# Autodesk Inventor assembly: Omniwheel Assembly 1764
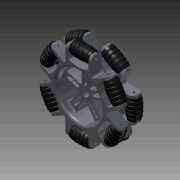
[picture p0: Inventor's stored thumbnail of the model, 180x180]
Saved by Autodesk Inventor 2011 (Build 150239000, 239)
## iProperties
Created: 2007-11
Part Number: Omniwheel Assembly 1764
Document SubType Name: Assembly
Designer: lwoods
Mass: 807.037 g
Surface Area: 1296.28 cm^2
Volume: 334.333 cm^3
Density: 2.41387 g/cm^3
Author: lwoods
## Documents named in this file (4)
- R:\CAD Archives\Wheels\Omniwheel\Omniwheel Assembly 1764.iam
- R:\CAD Archives\Wheels\Omniwheel\Omnidrive.ipt
- R:\CAD Archives\Wheels\Omniwheel\Roller Axle V4 1764.ipt
- R:\CAD Archives\Wheels\Omniwheel\roller assembly 1764.iam
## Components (25 placed, 3 different names)
1. Omnidrive:1 — Insert:1, Insert:2, Insert:3, Insert:4, Insert:5, Insert:6, Insert:7, Insert:8, Insert:9, Insert:10, Insert:11, Insert:12, Insert:16, Insert:17, Insert:19, Insert:20
2. Roller Axle V4 1764:1 — Insert:11, Insert:24
3. Roller Axle V4 1764:2 — Insert:8
4. Roller Axle V4 1764:3 — Insert:12, Insert:23
5. Roller Axle V4 1764:4 — Insert:10, Insert:22
6. Roller Axle V4 1764:5 — Insert:3, Insert:14
7. Roller Axle V4 1764:6 — Insert:4, Insert:18
8. Roller Axle V4 1764:7 — Insert:6
9. Roller Axle V4 1764:8 — Insert:2
10. Roller Axle V4 1764:9 — Insert:1, Insert:13
11. Roller Axle V4 1764:10 — Insert:5
12. Roller Axle V4 1764:11 — Insert:9, Insert:15
13. Roller Axle V4 1764:12 — Insert:7, Insert:21
14. roller assembly 1764:1 [sub-assembly] — Insert:18
15. roller assembly 1764:2 [sub-assembly] — Insert:20
16. roller assembly 1764:3 [sub-assembly] — Insert:17
17. roller assembly 1764:4 [sub-assembly] — Insert:19
18. roller assembly 1764:5 [sub-assembly] — Insert:21
19. roller assembly 1764:6 [sub-assembly] — Insert:22
20. roller assembly 1764:7 [sub-assembly] — Insert:23
21. roller assembly 1764:8 [sub-assembly] — Insert:24
22. roller assembly 1764:9 [sub-assembly] — Insert:16
23. roller assembly 1764:10 [sub-assembly] — Insert:15
24. roller assembly 1764:11 [sub-assembly] — Insert:13
25. roller assembly 1764:12 [sub-assembly] — Insert:14
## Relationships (24: Insert 24)
- Insert:1: Omnidrive:1 ↔ Roller Axle V4 1764:9
- Insert:2: Omnidrive:1 ↔ Roller Axle V4 1764:8
- Insert:3: Omnidrive:1 ↔ Roller Axle V4 1764:5
- Insert:4: Omnidrive:1 ↔ Roller Axle V4 1764:6
- Insert:5: Omnidrive:1 ↔ Roller Axle V4 1764:10
- Insert:6: Omnidrive:1 ↔ Roller Axle V4 1764:7
- Insert:7: Omnidrive:1 ↔ Roller Axle V4 1764:12
- Insert:8: Omnidrive:1 ↔ Roller Axle V4 1764:2
- Insert:9: Omnidrive:1 ↔ Roller Axle V4 1764:11
- Insert:10: Omnidrive:1 ↔ Roller Axle V4 1764:4
- Insert:11: Omnidrive:1 ↔ Roller Axle V4 1764:1
- Insert:12: Omnidrive:1 ↔ Roller Axle V4 1764:3
- Insert:13: Roller Axle V4 1764:9 ↔ roller assembly 1764:11
- Insert:14: Roller Axle V4 1764:5 ↔ roller assembly 1764:12
- Insert:15: Roller Axle V4 1764:11 ↔ roller assembly 1764:10
- Insert:16: Omnidrive:1 ↔ roller assembly 1764:9
- Insert:17: Omnidrive:1 ↔ roller assembly 1764:3
- Insert:18: Roller Axle V4 1764:6 ↔ roller assembly 1764:1
- Insert:19: Omnidrive:1 ↔ roller assembly 1764:4
- Insert:20: Omnidrive:1 ↔ roller assembly 1764:2
- Insert:21: Roller Axle V4 1764:12 ↔ roller assembly 1764:5
- Insert:22: Roller Axle V4 1764:4 ↔ roller assembly 1764:6
- Insert:23: Roller Axle V4 1764:3 ↔ roller assembly 1764:7
- Insert:24: Roller Axle V4 1764:1 ↔ roller assembly 1764:8
